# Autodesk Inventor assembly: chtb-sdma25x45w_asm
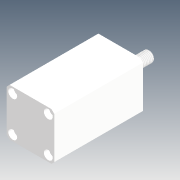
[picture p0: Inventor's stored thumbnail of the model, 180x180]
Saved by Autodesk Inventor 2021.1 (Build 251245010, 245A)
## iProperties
Company: Microsoft
Created: 2018-05
Part Number: chtb-sdma25x45w_asm
Description: STEP AP214
Document SubType Name: Assembly
Designer: user
Title: chtb-sdma25x45w_asm.STEP
Author: Windows
Revision Number: ÈÎºÎ
Sending System: SolidWorks 2015
Preprocessor: SwSTEP 2.0
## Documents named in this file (4)
- D:\Vault_2016\Projekty\Clamptek\Hydraulic\CHTB\CHTB-25\Inventor\chtb-sdma25x45w\chtb-sdma25x45w_asm.iam
- D:\Vault_2016\Projekty\Clamptek\Hydraulic\CHTB\CHTB-25\Inventor\chtb-sdma25x45w\CHTB-25QG.ipt
- D:\Vault_2016\Projekty\Clamptek\Hydraulic\CHTB\CHTB-25\Inventor\chtb-sdma25x45w\CHTB-SDMA25X45NBT.ipt
- D:\Vault_2016\Projekty\Clamptek\Hydraulic\CHTB\CHTB-25\Inventor\chtb-sdma25x45w\CHTB-SDMA25X45WHSG.ipt
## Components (3 placed, 3 different names)
1. CHTB-25QG_1
2. CHTB-SDMA25X45NBT_2
3. CHTB-SDMA25X45WHSG_3
